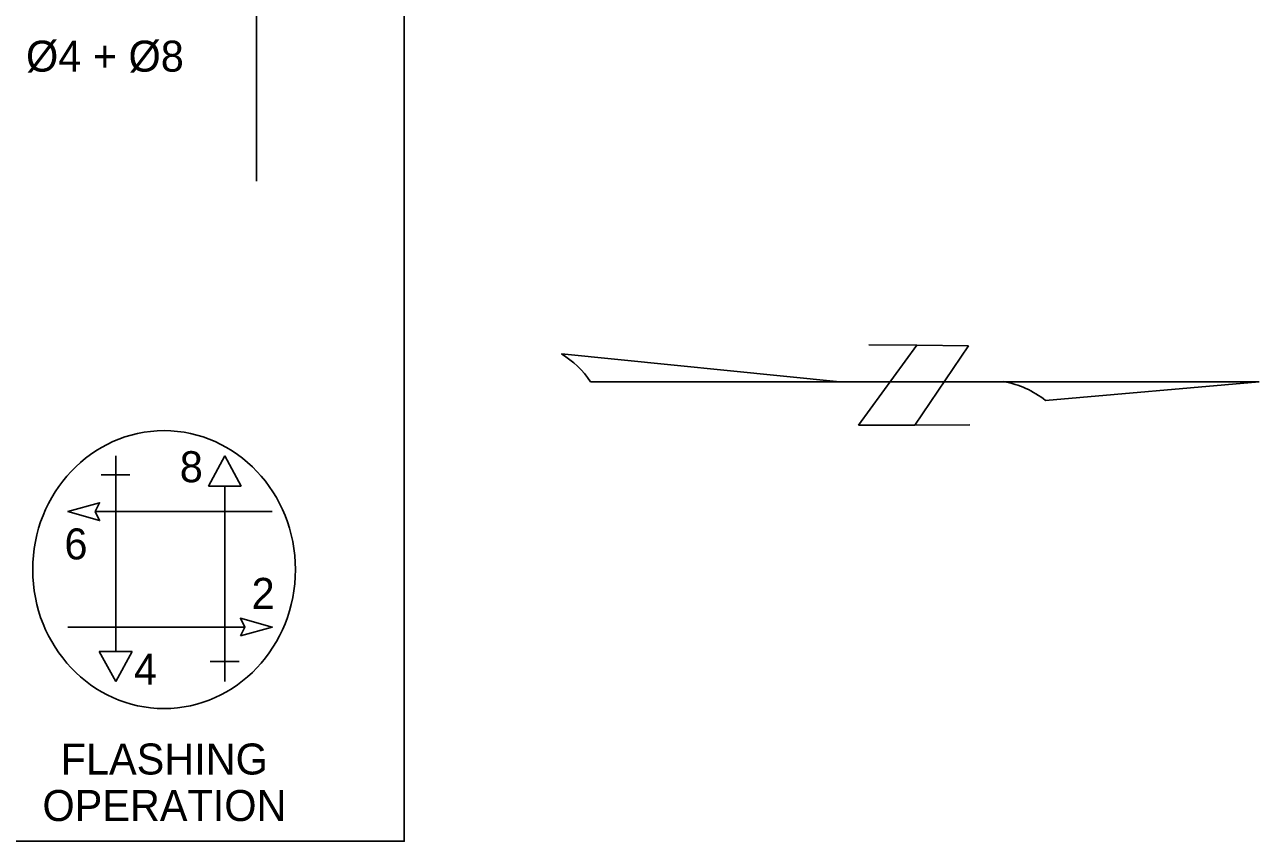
# Model space of a CAD drawing. Extents: x 0 to 3.01, y -0.05 to 1.83.
# Drawn here: x 1.1678 to 1.469, y 1.2827 to 1.4818 of the extents above; entities that cross this region are included whole.
import ezdxf

# ---------------------------------------------------------------- set-up
doc = ezdxf.new("R2010")
doc.units = 0
doc.layers.add('TR_TS_Border', color=7, linetype='Continuous')

msp = doc.modelspace()

# ---------------------------------------------------------------- linework, layer by layer
at = {"layer": 'TR_TS_Border'}
for p, q in [((1.22438, 1.57914), (1.22438, 1.44362)), ((1.37119, 1.38414), (1.38546, 1.40364)), ((1.37374, 1.40376), (1.38546, 1.40364)), ((1.39806, 1.40351), (1.38497, 1.38418)), ((1.38546, 1.40364), (1.39806, 1.40351)), ((1.36666, 1.39475), (1.29877, 1.40151)), ((1.30588, 1.39475), (1.36666, 1.39475)), ((1.36666, 1.39475), (1.40667, 1.39475)), ((1.40667, 1.39475), (1.469, 1.39475)), ((1.469, 1.39475), (1.41684, 1.39018)), ((1.38497, 1.38418), (1.37119, 1.38414)), ((1.38497, 1.38418), (1.39837, 1.38422)), ((1.19003, 1.3767), (1.19003, 1.32899)), ((1.21664, 1.3767), (1.21263, 1.36927)), ((1.22065, 1.36927), (1.21664, 1.3767)), ((1.18646, 1.372), (1.1935, 1.372)), ((1.21263, 1.36927), (1.22065, 1.36927)), ((1.21664, 1.36927), (1.21664, 1.32165)), ((1.22821, 1.36306), (1.18504, 1.36306)), ((1.17836, 1.33492), (1.22154, 1.33492)), ((1.19403, 1.32899), (1.18602, 1.32899)), ((1.18602, 1.32899), (1.19003, 1.32165)), ((1.19003, 1.32165), (1.19403, 1.32899)), ((1.21308, 1.32654), (1.22011, 1.32654))]:
    msp.add_line(p, q, dxfattribs=at)
msp.add_lwpolyline([(0.75574, 1.70195), (1.26043, 1.70195), (1.26043, 1.28268), (0.75574, 1.28268)], close=True, dxfattribs=at)
for points in [[(1.18504, 1.36306), (1.18611, 1.36522), (1.17836, 1.36306), (1.18611, 1.36089), (1.18504, 1.36306)], [(1.22047, 1.33275), (1.22821, 1.33492), (1.22047, 1.33708), (1.22154, 1.33492), (1.22047, 1.33275)]]:
    msp.add_lwpolyline(points, dxfattribs=at)
for centre, radius, start, end in [((1.28668, 1.38166), 0.02324, 34.2915, 58.6525), ((1.4027, 1.37237), 0.02274, 51.5602, 79.9558)]:
    msp.add_arc(centre, radius, start, end, dxfattribs=at)
msp.add_ellipse((1.20182, 1.34893), major_axis=(0, 0.03388), ratio=0.945811, dxfattribs=at)

# ---------------------------------------------------------------- texts
for s, height, p in [('Ø4 + Ø8', 0.007558, (1.16816, 1.47035)), ('8', 0.00756, (1.20566, 1.37024)), ('6', 0.00756, (1.17752, 1.35142)), ('2', 0.00756, (1.22318, 1.33935)), ('4', 0.00756, (1.19449, 1.3209)), ('FLASHING', 0.007558, (1.1766, 1.29897)), ('OPERATION', 0.007558, (1.17216, 1.28763))]:
    msp.add_text(s, height=height, dxfattribs=at).set_placement(p)

doc.saveas('drawing.dxf')
